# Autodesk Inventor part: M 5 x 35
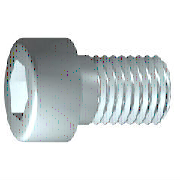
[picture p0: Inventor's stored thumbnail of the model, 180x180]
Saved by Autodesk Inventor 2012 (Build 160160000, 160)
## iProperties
IsCustomPart: 0
Company: 한국ATC센터
Created: 2014-12
Part Number: M 5 x 35
Material: 강, 연강
Description: 6각머리 태핑 나사
Document SubType Name: Modeling
Standard: KS B 1003
Designer: KYOUNG IL JANG
Standards Organization: KS
Language: ko-KR
Size Designation: M 5 x 35
Categories: <MemberInstance><Categories><Category DisplayName="조임쇠" InternalName="e4da775c-781d-43d5-af7c-5136215cf5a6" Mnemonic="FSTN"><Category DisplayName="볼트" InternalN
Density: 7.86 g/cm^3
Mass: 7.27786 g
Surface Area: 8.23857 cm^2
Volume: 0.925936 cm^3
Author: KYOUNG IL JANG
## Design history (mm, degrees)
revolve "본체" stored, may be unused: angle "d10" = 90 deg
sketch "스케치2"
  geometry: L1 (0, -5.95)-(0, 5.95) reference; L2 (-5.95, 0)-(5.95, 0) reference; L3 (2.309, 0)-(1.155, -2); L4 (1.155, -2)-(-1.155, -2); L5 (-1.155, -2)-(-2.309, 0); L6 (-2.309, 0)-(-1.155, 2); L7 (-1.155, 2)-(1.155, 2); L8 (1.155, 2)-(2.309, 0); 2 further points
  constraints: 12 end point, 1 coincident, 1 horizontal alignment, 1 point on line, 12 other
extrude "슬롯" join sketch "스케치2" stored distance "d11" = 10; taper "d12" = 0 deg
workplane "Work Plane1"
fillet "Fillet2" dims "d30" = 0.1 (= R)
body "Solid1"
fillet "모깎기1" dims "d17" = 0.5 (= RR)
feature "스레드" dims "d13" = 22 (= GEL), "d14" = 0
chamfer "모따기1" distance "d15" = 0.49076 (= -0.5 x SPD + 0.5 x GD); stored, may be unused: second distance "d16" = 0.49076 (= GUL), angle "d27" = 45 deg
sketch "스케치1"
  geometry: L1 (-1.167, 0)-(35, 0); L2 (35, 0)-(35, 2.5); L3 (35, 2.5)-(13, 2.5); L4 (13, 2.5)-(12.509, 2.5); L5 (12.509, 2.5)-(0, 2.5); L6 (0, 2.5)-(0, 4.25); L7 (0, 4.25)-(-5, 4.25); L8 (-5, 4.25)-(-5, 2.309); L9 (-5, 2.309)-(-2.5, 2.309); L10 (-2.5, 2.309)-(-1.167, 0); L11 (-13, 0)-(43, 0) reference; L12 (0, -0.85)-(0, 5.1) reference; L13 (13, 2.5)-(0, 2.5)
  constraints: 22 end point, 6 parallel, 2 collinear, 2 perpendicular, 1 horizontal, 1 point on line
  dimensions: "d1" = 22 distance from line of L3.end L2 (= GEL); "d2" = 0.49086 distance of L4.end L3.end (computed from GAL); "d3" = 5 distance between parallel lines of L8 L6 (= KOH); "d4" = 2.5 distance of L8.end L9.end (= INTI); "d5" = 60 deg angle of L10 L1; "d6" = 5 diameter of L3 L1 (= GD); "d7" = 5 diameter of L5 L1 (= BDM); "d8" = 4.6188 diameter of L9 L1 (= 1.1547 x SW); "d9" = 8.5 diameter of L7 L1 (= KOD); "d26" = 35 distance between parallel lines of L12 L2 (= NLG)
other parameters: "GD" = 5 (= NND) [user parameter; used in 2 equation terms], "NLG" = 35 [user parameter; used in 1 equation term], "GEL" = 22 [user parameter; used in 2 equation terms], "KOD" = 8.5 [user parameter; used in 1 equation term], "KOH" = 5 [user parameter; used in 1 equation term], "INTI" = 2.5 [user parameter; used in 1 equation term], "GAL" = 0.49076 (= 0.61345 x PTC) [user parameter; used in 1 equation term], "GUL" = 0.49076 (= 0.61345 x PTC) [user parameter; used in 1 equation term], "BDM" = 5 (= NND) [user parameter; used in 1 equation term], "SW" = 4 [user parameter; used in 2 equation terms], "RR" = 0.5 [user parameter; used in 1 equation term], "SPD" = 4.01848 (= NND - 1.2269 x PTC) [user parameter; used in 1 equation term], "d19" = 0, "d28" = 0, "d29" = 0, "R" = 0.1 [user parameter; used in 1 equation term], "PHH" = 0.2 [user parameter], "GD1" = 4.01848 (= THREADDIA - 1.2269 x PTC) [user parameter], "THREADDIA" = 5 [user parameter; used in 1 equation term], "FAWI" = 45 deg [user parameter], "TPU" = 12.5 (computed from PTC) [user parameter], "PTC" = 0.8 [user parameter; used in 5 equation terms], "NND" = 5 [user parameter; used in 3 equation terms], "TOA" = 30 deg [user parameter], "E0" = 4.62 (= 1.155 x SW) [user parameter]
